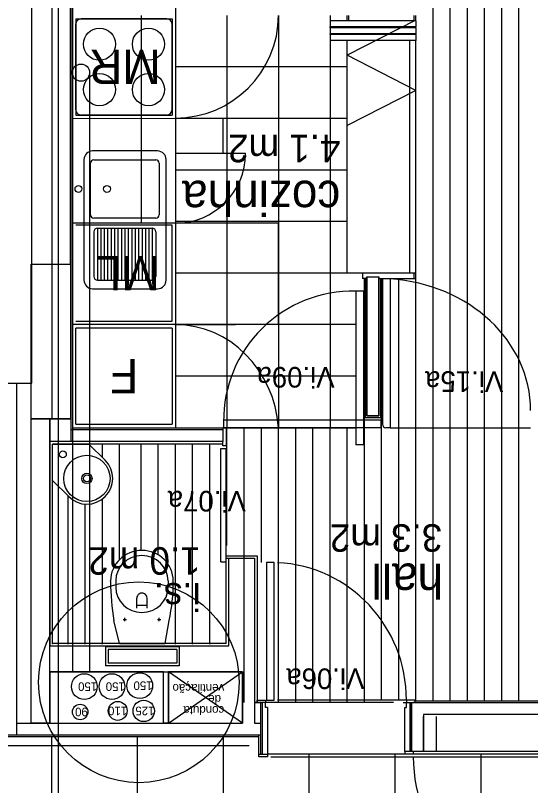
# Model space of a CAD drawing. Extents: x 1248 to 1356, y -443 to -224.
# Drawn here: x 1318.309 to 1321.309, y -238.907 to -234.424 of the extents above; entities that cross this region are included whole.
import ezdxf

# ---------------------------------------------------------------- set-up
doc = ezdxf.new("R2010")
doc.units = 0
for name, color, linetype in [('corte', 7, 'Continuous'), ('estereoctomias', 7, 'Continuous'), ('ind-pormenores', 7, 'Continuous'), ('Level 1', 7, 'Continuous'), ('Level 10', 7, 'Continuous'), ('Level 11', 7, 'Continuous'), ('Level 13', 7, 'Continuous'), ('Level 2', 7, 'Continuous'), ('Level 3', 7, 'Continuous'), ('Level 31', 7, 'Continuous'), ('Level 4', 7, 'Continuous'), ('Level 40', 7, 'Continuous'), ('Level 41', 7, 'Continuous'), ('Level 60', 7, 'Continuous'), ('mob-fixo', 7, 'Continuous'), ('revestimentos', 7, 'Continuous'), ('vermelhos-cont', 7, 'Continuous'), ('vista', 7, 'Continuous')]:
    doc.layers.add(name, color=color, linetype=linetype)

msp = doc.modelspace()

# ---------------------------------------------------------------- linework, layer by layer
at = {"layer": 'corte'}
for p, q in [((1318.5203, -232.264), (1318.5203, -236.7713)), ((1318.3144, -236.5639), (1318.3144, -238.614)), ((1318.4003, -238.544), (1318.4003, -236.5639)), ((1318.5103, -238.544), (1318.5103, -236.7713)), ((1319.551, -238.094), (1319.551, -237.584)), ((1318.5103, -238.094), (1319.551, -238.094)), ((1319.631, -238.244), (1319.631, -238.544)), ((1320.616, -238.424), (1323.801, -238.424)), ((1319.736, -238.614), (1318.2044, -238.614))]:
    msp.add_line(p, q, dxfattribs=at)
for points in [[(1318.2044, -236.5639), (1318.4044, -236.5639), (1318.4044, -232.0639), (1318.2044, -232.0639)], [(1318.2044, -236.5639), (1318.4044, -236.5639), (1318.4044, -232.0639), (1318.2044, -232.0639)], [(1318.4003, -235.8713), (1318.6303, -235.8713), (1318.6303, -236.7713), (1318.4003, -236.7713)]]:
    msp.add_lwpolyline(points, close=True, dxfattribs=at)
at = {"layer": 'estereoctomias'}
for p, q in [((1319.701, -237.584), (1319.701, -238.424)), ((1319.701, -238.424), (1319.7435, -238.424)), ((1320.576, -238.724), (1319.776, -238.724))]:
    msp.add_line(p, q, dxfattribs=at)
for points in [[(1318.5203, -232.264), (1318.5203, -235.8713), (1318.6303, -235.8713), (1318.6303, -232.264)], [(1320.426, -236.754), (1320.356, -236.754), (1320.356, -235.946), (1320.426, -235.946), (1320.426, -236.754)], [(1319.701, -237.584), (1319.701, -238.424), (1319.736, -238.424), (1319.736, -238.614), (1318.2044, -238.614), (1318.2044, -236.5639), (1318.3144, -236.5639), (1318.3144, -238.544), (1319.631, -238.544), (1319.631, -238.244), (1319.201, -238.244), (1319.201, -238.544), (1319.171, -238.544), (1319.171, -238.244), (1318.5103, -238.244), (1318.5103, -238.5239), (1318.5103, -238.544), (1318.4003, -238.544), (1318.4003, -236.7713), (1318.5103, -236.7713), (1318.5103, -238.094), (1319.551, -238.094), (1319.551, -237.584)], [(1319.516, -236.834), (1319.516, -236.904), (1318.5103, -236.904), (1318.5103, -236.7713), (1318.631, -236.7713), (1318.631, -236.834)], [(1321.596, -238.494), (1321.596, -238.544), (1321.526, -238.544), (1321.526, -238.494), (1320.686, -238.494), (1320.686, -238.709), (1320.616, -238.709), (1320.616, -238.424), (1323.801, -238.424), (1323.801, -236.7713), (1323.871, -236.7713), (1323.871, -238.494)]]:
    msp.add_lwpolyline(points, close=True, dxfattribs=at)
at = {"layer": 'ind-pormenores'}
msp.add_circle((1319.0278, -238.3059), 0.5842, dxfattribs=at)
at = {"layer": 'Level 1'}
for p, q in [((1318.631, -232.264), (1318.631, -236.904)), ((1320.241, -234.456), (1320.241, -234.424)), ((1320.641, -234.456), (1320.241, -234.456)), ((1320.251, -234.456), (1320.251, -234.424)), ((1320.631, -234.456), (1320.631, -234.424)), ((1320.641, -234.456), (1320.641, -234.424)), ((1320.641, -235.924), (1320.331, -235.924)), ((1320.331, -235.924), (1320.331, -235.956)), ((1320.441, -235.924), (1320.341, -235.924)), ((1320.631, -235.956), (1320.631, -235.924)), ((1320.641, -235.956), (1320.641, -235.924)), ((1320.356, -235.956), (1320.331, -235.956)), ((1320.356, -235.946), (1320.356, -236.754)), ((1320.356, -235.946), (1320.426, -235.946)), ((1320.426, -236.754), (1320.426, -235.946)), ((1320.426, -235.956), (1320.641, -235.956)), ((1320.356, -236.754), (1320.426, -236.754)), ((1318.631, -236.834), (1319.516, -236.834)), ((1319.516, -236.824), (1319.516, -236.904)), ((1319.516, -236.904), (1318.5103, -236.904)), ((1319.536, -237.584), (1319.701, -237.584)), ((1319.701, -237.584), (1319.701, -238.544)), ((1318.5103, -238.244), (1319.631, -238.244)), ((1319.171, -238.544), (1319.171, -238.244)), ((1319.201, -238.544), (1319.201, -238.244)), ((1319.736, -238.424), (1319.701, -238.424)), ((1319.736, -238.424), (1319.736, -238.614)), ((1320.616, -238.424), (1320.616, -238.709)), ((1320.686, -238.494), (1320.686, -238.709)), ((1321.526, -238.494), (1320.686, -238.494)), ((1318.3144, -238.544), (1319.631, -238.544)), ((1319.701, -238.544), (1319.736, -238.544)), ((1320.686, -238.709), (1320.616, -238.709))]:
    msp.add_line(p, q, dxfattribs=at)
at = {"layer": 'Level 10'}
for p, q in [((1320.741, -238.414), (1320.741, -232.274)), ((1320.841, -238.414), (1320.841, -232.274)), ((1320.941, -238.414), (1320.941, -232.274)), ((1321.041, -238.414), (1321.041, -232.274)), ((1321.141, -238.414), (1321.141, -232.274)), ((1321.241, -238.414), (1321.241, -232.274)), ((1319.541, -234.424), (1319.541, -236.824)), ((1319.841, -234.424), (1319.841, -236.824)), ((1320.141, -234.424), (1320.141, -236.824)), ((1320.241, -234.724), (1319.241, -234.724)), ((1320.241, -235.024), (1319.241, -235.024)), ((1320.241, -235.324), (1319.241, -235.324)), ((1320.241, -235.624), (1319.241, -235.624)), ((1319.841, -236.224), (1319.841, -235.634)), ((1320.291, -235.924), (1319.241, -235.924)), ((1320.341, -238.424), (1320.341, -235.956)), ((1320.441, -238.409), (1320.441, -235.956)), ((1320.541, -238.409), (1320.541, -235.956)), ((1320.641, -238.414), (1320.641, -235.956)), ((1320.291, -236.224), (1319.241, -236.224)), ((1320.291, -236.524), (1319.241, -236.524)), ((1319.521, -236.824), (1320.291, -236.824)), ((1319.541, -237.509), (1319.541, -236.824)), ((1319.641, -238.424), (1319.641, -236.824)), ((1319.741, -237.609), (1319.741, -236.824)), ((1319.841, -238.424), (1319.841, -236.824)), ((1319.941, -238.424), (1319.941, -236.824)), ((1320.041, -238.424), (1320.041, -236.824)), ((1320.141, -238.424), (1320.141, -236.824)), ((1320.241, -238.424), (1320.241, -236.824)), ((1318.8153, -236.9968), (1318.8153, -236.919)), ((1318.9153, -237.5916), (1318.9153, -236.919)), ((1319.041, -237.5383), (1319.041, -236.919)), ((1319.141, -237.5645), (1319.141, -236.919)), ((1319.241, -238.084), (1319.241, -236.919)), ((1319.341, -238.084), (1319.341, -236.919)), ((1319.441, -238.084), (1319.441, -236.919)), ((1318.6153, -238.084), (1318.6153, -237.2211)), ((1318.8153, -238.084), (1318.8153, -237.239)), ((1318.7153, -238.084), (1318.7153, -237.2689)), ((1320.511, -238.424), (1319.711, -238.424)), ((1318.5183, -238.624), (1318.5183, -240.224)), ((1319.0183, -238.624), (1319.0183, -240.224)), ((1319.5183, -238.624), (1319.5183, -240.224)), ((1313.7069, -238.674), (1319.671, -238.674)), ((1320.0183, -238.724), (1320.0183, -240.124)), ((1320.5183, -238.724), (1320.5183, -240.224)), ((1321.0183, -238.724), (1321.0183, -240.124))]:
    msp.add_line(p, q, dxfattribs=at)
at = {"layer": 'Level 11'}
for p, q in [((1319.1911, -234.444), (1318.6911, -234.444)), ((1318.6611, -234.974), (1318.6611, -234.474)), ((1319.2211, -234.974), (1319.2211, -234.474)), ((1319.1911, -235.004), (1318.6911, -235.004)), ((1318.7661, -235.2644), (1319.1261, -235.2644)), ((1318.7461, -235.5844), (1318.7461, -235.2844)), ((1319.1461, -235.2844), (1319.1461, -235.5844)), ((1319.1261, -235.6044), (1318.7661, -235.6044)), ((1318.7861, -235.6628), (1319.1061, -235.6628)), ((1318.7861, -235.6628), (1318.7861, -235.9644)), ((1318.8061, -235.6628), (1318.8061, -235.9644)), ((1318.8261, -235.6628), (1318.8261, -235.9644)), ((1318.8461, -235.6628), (1318.8461, -235.9644)), ((1318.8661, -235.6628), (1318.8661, -235.9644)), ((1318.8861, -235.6628), (1318.8861, -235.9644)), ((1318.9061, -235.6628), (1318.9061, -235.9644)), ((1318.9261, -235.6628), (1318.9261, -235.9644)), ((1318.9461, -235.6628), (1318.9461, -235.9644)), ((1318.9661, -235.6628), (1318.9661, -235.9644)), ((1318.9861, -235.6628), (1318.9861, -235.9644)), ((1319.0061, -235.6628), (1319.0061, -235.9644)), ((1319.0261, -235.6628), (1319.0261, -235.9644)), ((1319.0461, -235.6628), (1319.0461, -235.9644)), ((1319.0661, -235.6628), (1319.0661, -235.9644)), ((1319.0861, -235.6628), (1319.0861, -235.9644)), ((1319.1061, -235.6628), (1319.1061, -235.9644)), ((1318.7661, -235.6828), (1318.7661, -235.9444)), ((1319.1261, -235.6828), (1319.1261, -235.9444)), ((1318.7861, -235.9644), (1319.1061, -235.9644)), ((1319.221, -236.244), (1318.661, -236.244)), ((1318.661, -236.804), (1318.661, -236.244)), ((1319.221, -236.244), (1319.221, -236.804)), ((1318.661, -236.804), (1319.221, -236.804)), ((1318.5253, -236.919), (1318.7374, -236.919)), ((1318.5253, -237.1311), (1318.5253, -236.919)), ((1318.8313, -237.0129), (1318.7374, -236.919)), ((1318.6192, -237.225), (1318.5253, -237.1311)), ((1318.8632, -237.7192), (1318.8631, -237.7155)), ((1318.8931, -237.7158), (1318.8931, -237.7519)), ((1319.1981, -237.7158), (1319.1981, -237.7519)), ((1319.2281, -237.7192), (1319.2281, -237.7155)), ((1319.0156, -237.8738), (1319.0156, -237.8166)), ((1319.0756, -237.8738), (1319.0756, -237.8165)), ((1319.0156, -237.8561), (1319.0756, -237.8561)), ((1318.9158, -238.079), (1318.8817, -237.9462)), ((1318.9356, -237.9401), (1318.9556, -237.9401)), ((1318.9456, -237.9501), (1318.9456, -237.9301)), ((1319.1356, -237.9401), (1319.1556, -237.9401)), ((1319.1456, -237.9501), (1319.1456, -237.9301)), ((1319.1804, -238.079), (1319.2046, -237.9462)), ((1318.9158, -238.079), (1319.1804, -238.079)), ((1318.8331, -238.099), (1318.8331, -238.209)), ((1319.2631, -238.099), (1318.8331, -238.099)), ((1319.2481, -238.114), (1318.8481, -238.114)), ((1318.8481, -238.114), (1318.8481, -238.194)), ((1319.2481, -238.114), (1319.2481, -238.194)), ((1319.2631, -238.099), (1319.2631, -238.209)), ((1319.2631, -238.209), (1318.8331, -238.209)), ((1319.2481, -238.194), (1318.8481, -238.194))]:
    msp.add_line(p, q, dxfattribs=at)
for points in [[(1319.1367, -235.2132), (1318.7583, -235.2132)], [(1318.7083, -235.2632), (1318.7083, -235.9646)], [(1319.1867, -235.9646), (1319.1867, -235.2632)], [(1318.7583, -236.0146), (1319.1367, -236.0146)]]:
    msp.add_lwpolyline(points, dxfattribs=at)
for centre, radius in [((1318.7985, -234.5918), 0.0936), ((1319.0837, -234.5918), 0.0936), ((1318.7985, -234.8561), 0.0936), ((1319.0837, -234.8561), 0.0936), ((1318.6762, -235.4344), 0.0199), ((1318.8421, -235.4344), 0.0199), ((1318.5853, -236.979), 0.02), ((1318.7253, -237.119), 0.135), ((1318.7253, -237.119), 0.03), ((1318.7253, -237.119), 0.02)]:
    msp.add_circle(centre, radius, dxfattribs=at)
for centre, radius, start, end in [((1318.6911, -234.474), 0.03, 90, 179.9998), ((1319.1911, -234.474), 0.03, 360, 89.9999), ((1318.6911, -234.974), 0.03, 179.9998, 270.0001), ((1319.1911, -234.974), 0.03, 269.9999, 359.9999), ((1318.7583, -235.2632), 0.05, 90, 180), ((1319.1367, -235.2632), 0.05, 0, 90), ((1318.7661, -235.2844), 0.02, 90, 180), ((1319.1261, -235.2844), 0.02, 0, 90), ((1318.7661, -235.5844), 0.02, 180, 270), ((1319.1261, -235.5844), 0.02, 270, 0), ((1318.7861, -235.6828), 0.02, 90, 180), ((1319.1061, -235.6828), 0.02, 0, 90), ((1318.7583, -235.9646), 0.05, 180, 270), ((1318.7861, -235.9444), 0.02, 180, 270), ((1319.1061, -235.9444), 0.02, 270, 0), ((1319.1367, -235.9646), 0.05, 270, 0), ((1318.7253, -237.119), 0.15, 225.0002, 45), ((1319.0456, -237.8167), 0.03, 359.9987, 180.0005)]:
    msp.add_arc(centre, radius, start, end, dxfattribs=at)
for centre, major_axis, ratio, start_param, end_param in [((1319.0456, -237.7158), (0.1825, 0), 0.972581, 0.000002, 3.141589), ((1319.0456, -237.7158), (0.1525, 0), 0.967187, 0.000002, 3.141589), ((1320.2627, -237.7192), (0, 1.4), 0.999692, 1.570794, 1.733712), ((1317.4498, -237.7192), (1.7783, 0), 0.787256, 6.120268, 6.283186), ((1319.0456, -237.7519), (0.1525, 0), 0.967187, 3.141595, 6.283182)]:
    msp.add_ellipse(centre, major_axis=major_axis, ratio=ratio, start_param=start_param, end_param=end_param, dxfattribs=at)
at = {"layer": 'Level 13'}
for p, q in [((1319.241, -233.727), (1319.241, -236.824)), ((1320.141, -234.456), (1320.141, -234.491)), ((1320.241, -234.456), (1320.141, -234.456)), ((1320.641, -234.456), (1320.641, -234.491)), ((1320.641, -234.491), (1320.141, -234.491)), ((1320.641, -234.496), (1320.141, -234.496)), ((1320.141, -234.496), (1320.141, -234.531)), ((1320.641, -234.496), (1320.641, -234.531)), ((1320.641, -234.531), (1320.141, -234.531)), ((1320.641, -234.536), (1320.141, -234.536)), ((1320.141, -234.536), (1320.141, -234.571)), ((1320.641, -234.536), (1320.641, -234.571)), ((1320.641, -234.571), (1320.141, -234.571)), ((1320.446, -235.9582), (1320.446, -236.804)), ((1320.491, -235.9582), (1320.446, -235.9582)), ((1320.491, -235.9582), (1320.491, -236.824)), ((1320.336, -236.029), (1320.291, -236.029)), ((1320.291, -236.029), (1320.291, -236.924)), ((1320.336, -236.029), (1320.336, -236.924)), ((1319.241, -236.224), (1318.641, -236.224)), ((1320.491, -236.824), (1320.466, -236.824)), ((1320.336, -236.924), (1320.291, -236.924)), ((1319.506, -236.944), (1319.536, -236.944)), ((1319.506, -237.604), (1319.506, -236.944)), ((1319.516, -236.944), (1319.536, -236.944)), ((1319.536, -237.604), (1319.536, -236.944)), ((1319.536, -237.569), (1319.716, -237.569)), ((1319.716, -237.569), (1319.716, -238.424)), ((1319.506, -237.604), (1319.536, -237.604)), ((1319.771, -237.609), (1319.771, -238.409)), ((1319.815, -237.609), (1319.771, -237.609)), ((1319.815, -238.409), (1319.815, -237.609)), ((1319.716, -238.409), (1319.766, -238.409)), ((1319.716, -238.419), (1319.716, -238.409)), ((1319.721, -238.419), (1319.716, -238.419)), ((1319.721, -238.424), (1319.721, -238.419)), ((1319.766, -238.424), (1319.721, -238.424)), ((1319.746, -238.424), (1319.746, -238.724)), ((1319.766, -238.409), (1319.766, -238.424)), ((1319.766, -238.453), (1319.766, -238.424)), ((1319.776, -238.453), (1319.766, -238.453)), ((1319.771, -238.409), (1319.815, -238.409)), ((1319.776, -238.453), (1319.776, -238.724)), ((1320.566, -238.424), (1320.586, -238.424)), ((1320.576, -238.709), (1320.576, -238.453)), ((1320.576, -238.453), (1320.586, -238.453)), ((1320.636, -238.409), (1320.586, -238.409)), ((1320.586, -238.409), (1320.586, -238.424)), ((1320.586, -238.424), (1320.631, -238.424)), ((1320.586, -238.453), (1320.586, -238.424)), ((1320.606, -238.424), (1320.606, -238.709)), ((1320.631, -238.424), (1320.631, -238.419)), ((1320.631, -238.419), (1320.636, -238.419)), ((1320.636, -238.419), (1320.636, -238.409)), ((1320.616, -238.504), (1320.606, -238.504)), ((1319.726, -238.739), (1319.726, -238.614)), ((1319.736, -238.614), (1319.736, -238.724)), ((1321.481, -238.709), (1320.576, -238.709)), ((1320.576, -238.709), (1320.576, -238.724)), ((1320.626, -238.709), (1320.626, -238.724)), ((1319.726, -238.724), (1319.776, -238.724)), ((1319.776, -238.739), (1319.726, -238.739)), ((1319.776, -238.724), (1319.776, -238.739)), ((1320.626, -238.724), (1320.576, -238.724)), ((1321.481, -238.724), (1320.616, -238.724)), ((1321.481, -238.724), (1320.616, -238.724)), ((1321.481, -238.724), (1320.626, -238.724))]:
    msp.add_line(p, q, dxfattribs=at)
msp.add_arc((1320.466, -236.804), 0.02, 180, 270, dxfattribs=at)
at = {"layer": 'Level 2'}
for p, q in [((1320.141, -234.496), (1320.141, -234.491)), ((1320.641, -234.496), (1320.641, -234.491)), ((1320.141, -234.536), (1320.141, -234.531)), ((1320.641, -234.536), (1320.641, -234.531)), ((1320.241, -235.924), (1320.241, -234.571)), ((1320.641, -235.924), (1320.641, -234.5671)), ((1320.341, -235.924), (1320.241, -235.924))]:
    msp.add_line(p, q, dxfattribs=at)
at = {"layer": 'Level 3'}
for p, q in [((1319.041, -234.424), (1319.041, -235.634)), ((1319.241, -235.634), (1318.641, -235.634))]:
    msp.add_line(p, q, dxfattribs=at)
at = {"layer": 'Level 31'}
for p, q in [((1319.536, -236.824), (1319.516, -236.824)), ((1319.536, -236.824), (1319.536, -236.929)), ((1319.536, -236.929), (1319.516, -236.929))]:
    msp.add_line(p, q, dxfattribs=at)
at = {"layer": 'Level 4'}
for p, q in [((1318.661, -234.444), (1319.221, -234.444)), ((1318.661, -234.444), (1318.661, -235.004)), ((1319.221, -234.444), (1319.221, -235.004)), ((1320.641, -234.4521), (1320.241, -234.6563)), ((1320.606, -235.924), (1320.606, -234.5671)), ((1320.641, -234.8606), (1320.241, -234.6563)), ((1320.641, -234.8606), (1320.241, -235.0648)), ((1318.641, -235.024), (1319.241, -235.0216)), ((1318.661, -235.004), (1319.221, -235.004)), ((1319.241, -235.0216), (1319.5185, -235.0216)), ((1319.5185, -235.226), (1319.5185, -235.0216)), ((1319.241, -235.226), (1319.649, -235.226)), ((1319.221, -235.644), (1318.661, -235.644)), ((1319.221, -236.204), (1319.221, -235.644)), ((1319.841, -235.634), (1319.241, -235.634)), ((1318.661, -236.204), (1319.221, -236.204)), ((1319.241, -236.224), (1319.591, -236.224)), ((1320.436, -236.779), (1319.521, -236.779)), ((1319.521, -236.789), (1319.521, -236.824)), ((1320.436, -236.779), (1320.436, -236.824)), ((1320.436, -236.824), (1319.521, -236.824)), ((1320.491, -236.824), (1321.309, -236.824)), ((1320.586, -238.409), (1319.835, -238.409)), ((1320.6835, -238.504), (1320.6835, -238.709)), ((1320.7585, -238.504), (1320.7585, -238.709)), ((1319.796, -238.739), (1321.481, -238.739))]:
    msp.add_line(p, q, dxfattribs=at)
for centre, radius, start, end in [((1319.241, -234.4216), 0.6, 270, 359.7775), ((1319.241, -235.226), 0.408, 270, 0), ((1320.2752, -236.7828), 0.7542, 88.8015, 180.4703)]:
    msp.add_arc(centre, radius, start, end, dxfattribs=at)
for centre, major_axis, ratio, start_param, end_param in [((1320.4256, -236.724), (-0.8834, 0), 0.869285, 3.141609, 4.638298), ((1319.241, -236.8748), (0, 0.6509), 0.924693, 4.790593, 6.283185), ((1319.8009, -238.409), (0, -0.8), 0.981405, 1.570796, 3.098101), ((1321.481, -238.739), (-0.8551, 0), 0.999998, 0, 1.570796)]:
    msp.add_ellipse(centre, major_axis=major_axis, ratio=ratio, start_param=start_param, end_param=end_param, dxfattribs=at)
at = {"layer": 'Level 41'}
for p, q in [((1319.631, -238.544), (1319.201, -238.244)), ((1319.201, -238.544), (1319.631, -238.244))]:
    msp.add_line(p, q, dxfattribs=at)
for centre, radius in [((1318.7103, -238.3309), 0.075), ((1318.8713, -238.3309), 0.075), ((1319.033, -238.3254), 0.075), ((1318.6858, -238.4785), 0.045), ((1318.9046, -238.4723), 0.055), ((1319.0563, -238.4723), 0.0625)]:
    msp.add_circle(centre, radius, dxfattribs=at)
at = {"layer": 'mob-fixo'}
for p, q in [((1318.641, -234.7569), (1318.641, -238.244)), ((1318.741, -234.7569), (1318.741, -238.244))]:
    msp.add_line(p, q, dxfattribs=at)
msp.add_circle((1318.691, -234.7569), 0.05, dxfattribs=at)
at = {"layer": 'revestimentos'}
for p, q in [((1318.641, -232.274), (1318.641, -236.824)), ((1320.346, -235.956), (1320.346, -236.764)), ((1320.436, -236.764), (1320.436, -235.956)), ((1320.346, -236.764), (1320.436, -236.764)), ((1318.641, -236.824), (1319.516, -236.824)), ((1319.516, -236.919), (1318.5253, -236.919)), ((1318.5253, -238.084), (1318.5253, -236.919)), ((1319.536, -238.079), (1319.536, -237.584)), ((1319.536, -238.079), (1318.5253, -238.079)), ((1320.636, -238.414), (1323.791, -238.414)), ((1319.726, -238.624), (1318.1944, -238.624))]:
    msp.add_line(p, q, dxfattribs=at)
at = {"layer": 'vermelhos-cont'}
msp.add_line((1318.5594, -250.7923), (1318.5594, -229.6198), dxfattribs=at)
at = {"layer": 'vista'}
msp.add_line((1319.516, -236.929), (1319.516, -236.904), dxfattribs=at)

# ---------------------------------------------------------------- texts
at = {"layer": 'Level 11'}
for s, p in [('MR', (1319.1547, -234.624)), ('ML', (1319.1488, -235.824)), ('F', (1319.025, -236.424))]:
    msp.add_text(s, height=0.2, rotation=180, dxfattribs=at).set_placement(p)
at = {"layer": 'Level 40'}
for s, p in [('Vi.09a', (1320.1679, -236.4702)), ('Vi.15a', (1321.1496, -236.4951)), ('Vi.07a', (1319.651, -237.1915)), ('Vi.06a', (1320.3415, -238.2249))]:
    msp.add_text(s, height=0.12, rotation=180, dxfattribs=at).set_placement(p)
at = {"layer": 'Level 41'}
for s, p in [('150', (1318.7853, -238.3059)), ('150', (1318.9463, -238.3059)), ('150', (1319.108, -238.3004)), ('ventilação ', (1319.525, -238.3155)), (' de ', (1319.525, -238.3799)), ('90', (1318.7308, -238.4535)), ('110', (1318.9596, -238.4473)), ('125', (1319.1188, -238.4473)), ('conduta', (1319.525, -238.4444))]:
    msp.add_text(s, height=0.05, rotation=180, dxfattribs=at).set_placement(p)
at = {"layer": 'Level 60'}
for s, height, p in [('4.1 m2', 0.16, (1320.2013, -235.1187)), ('cozinha', 0.2, (1320.2013, -235.3865)), ('3.3 m2', 0.16, (1320.7944, -237.3856)), ('1.0 m2', 0.16, (1319.3876, -237.5192)), ('hall', 0.2, (1320.7992, -237.6144)), ('i.s.', 0.16, (1319.3876, -237.7282))]:
    msp.add_text(s, height=height, rotation=180, dxfattribs=at).set_placement(p)

doc.saveas('drawing.dxf')
